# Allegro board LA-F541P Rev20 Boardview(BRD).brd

Outline 352.7 x 123.3 mm; copper layers: TOP, GND1, IN1, IN2, GND2, IN3, IN4, VCC, IN5, IN6, GND3, BOTTOM. Coordinates in mm from the lower left corner of the outline.

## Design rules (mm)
constraint set DEFAULT: min track width 0.14
net group CHR_USB20_1: nets CHR_USB20_N1 CHR_USB20_P1
net group CHR_USB20_1_R: nets CHR_USB20_N1_R CHR_USB20_P1_R
net group CHR_USB20_2: nets CHR_USB20_N2 CHR_USB20_P2
net group CHR_USB20_2_R: nets CHR_USB20_N2_R CHR_USB20_P2_R
net group CPU_DP3_0: nets CPU_DP3_N0 CPU_DP3_P0
net group CPU_DP3_1: nets CPU_DP3_N1 CPU_DP3_P1
net group CPU_DP3_2: nets CPU_DP3_N2 CPU_DP3_P2
net group CPU_DP3_3: nets CPU_DP3_N3 CPU_DP3_P3
net group CPU_DP3_AUX: nets CPU_DP3_AUXN CPU_DP3_AUXP
net group CPU_DP3_AUX_R: nets CPU_DP3_AUXN_R CPU_DP3_AUXP_R
net group CSI_ISL88738: nets CSIN_ISL88738 CSIP_ISL88738
net group CSO_ISL88738: nets CSON_ISL88738 CSOP_ISL88738
net group DIFFPAIR49: nets SD_RCLK_M SD_RCLK_P
net group DIFFPAIR63: nets TBT_DDC_CLK TBT_DDC_DATA
net group DIFFPAIR69: nets DDI1_DDPB_CTRLCLK DDI1_DDPB_CTRLDAT
net group DIFFPAIR70: nets DDI2_DDPC_CTRLCLK DDI2_DDPC_CTRLDAT
net group DIFFPAIR71: nets DTH_CSCL DTH_CSDA
net group DIFFPAIR79: nets I2C1_SCK_TP I2C1_SDA_TP
net group DIFFPAIR97: nets MSCLK MSDATA
net group DIFFPAIR98: nets MSCLK_R MSDATA_R
net group DIFFPAIR107: nets CPU_DP3_N0_C CPU_DP3_P0_C
net group DIFFPAIR108: nets CPU_DP3_N1_C CPU_DP3_P1_C
net group DIFFPAIR109: nets CPU_DP3_N2_C CPU_DP3_P2_C
net group DIFFPAIR110: nets CPU_DP3_N3_C CPU_DP3_P3_C
net group DIFFPAIR115: nets CPU_DP3_AUXN_C CPU_DP3_AUXP_C
net group DIFFPAIR120: nets PCIE_PRX_DTX_N11 PCIE_PRX_DTX_P11
net group DIFFPAIR122: nets VCCSENSE_VGA VSSSENSE_VGA
net group DIFFPAIR123: nets VCCGT_SENSE VSSGT_SENSE
net group DIFFPAIR124: nets VCC_SENSE VSS_SENSE
net group DIFFPAIR125: nets VCC_SENSE_R VSS_SENSE_R
net group DIFFPAIR126: nets VCCGT_SENSE_R VSSGT_SENSE_R
net group DIFFPAIR129: nets I2C0_SCK_TS_R I2C0_SDA_TS_R
net group DIFFPAIR130: nets PBAT_CHARGER_SMBCLK PBAT_CHARGER_SMBDAT
net group DIFFPAIR131: nets GPU_SMBCLK GPU_SMBDAT
net group DIFFPAIR132: nets MEM_SMBCLK MEM_SMBDATA
net group DIFFPAIR133: nets N128727776 N128727796
net group EDP_AUXP_C: nets EDP_AUXN_C EDP_AUXP_C
net group EDP_TX3_R: nets EDP_TXN3_R EDP_TXP3_R
net group EDP_TXP2_R: nets EDP_TXN2_R EDP_TXP2_R
net group ESPI_CLK: nets ESPI_CLK ESPI_CLK_5105
net group ESPI_IO0: nets ESPI_IO0 ESPI_IO0_R
net group ESPI_IO1: nets ESPI_IO1 ESPI_IO1_R
net group ESPI_IO2: nets ESPI_IO2 ESPI_IO2_R
net group ESPI_IO3: nets ESPI_IO3 ESPI_IO3_R
net group ESPI_RESET#: nets ESPI_RESET# ESPI_RESET#_R
net group FBA_CLK0: nets FBA_CLK0 FBA_CLK0#
net group FBA_CLK1: nets FBA_CLK1 FBA_CLK1#
net group FBA_WCK0: nets FBA_WCK0 FBA_WCK0_N
net group FBA_WCK1: nets FBA_WCK1 FBA_WCK1_N
net group FBA_WCK2: nets FBA_WCK2 FBA_WCK2_N
net group FBA_WCK3: nets FBA_WCK3 FBA_WCK3_N
net group FBC_CLK0: nets FBC_CLK0 FBC_CLK0#
net group FBC_CLK1: nets FBC_CLK1 FBC_CLK1#
net group FBC_WCK0: nets FBC_WCK0 FBC_WCK0_N
net group FBC_WCK1: nets FBC_WCK1 FBC_WCK1_N
net group FBC_WCK2: nets FBC_WCK2 FBC_WCK2_N
net group FBC_WCK3: nets FBC_WCK3 FBC_WCK3_N
net group HDMI-DDC: nets DDC_CLK_HDMI DDC_DAT_HDMI
net group ISUM_GT: nets ISUMN_GT ISUMP_GT
net group ISUM_SA: nets ISUMN_SA ISUMP_SA
net group ISUM_VCORE: nets ISUMN_VCORE ISUMP_VCORE
net group LPC_CLK: nets PCI_CLK_LPC1 PCI_CLK_LPC1_R
net group PCIE_PRX_C_TTX_17: nets PCIE_PRX_C_TTX_N17 PCIE_PRX_C_TTX_P17
net group PCIE_PRX_C_TTX_18: nets PCIE_PRX_C_TTX_N18 PCIE_PRX_C_TTX_P18
net group PCIE_PRX_C_TTX_19: nets PCIE_PRX_C_TTX_N19 PCIE_PRX_C_TTX_P19
net group PCIE_PRX_C_TTX_20: nets PCIE_PRX_C_TTX_N20 PCIE_PRX_C_TTX_P20
net group PCIE_PRX_TTX_17: nets PCIE_PRX_TTX_N17 PCIE_PRX_TTX_P17
net group PCIE_PRX_TTX_18: nets PCIE_PRX_TTX_N18 PCIE_PRX_TTX_P18
net group PCIE_PRX_TTX_19: nets PCIE_PRX_TTX_N19 PCIE_PRX_TTX_P19
net group PCIE_PRX_TTX_20: nets PCIE_PRX_TTX_N20 PCIE_PRX_TTX_P20
net group PCIE_PTX_C_TRX_17: nets PCIE_PTX_C_TRX_N17 PCIE_PTX_C_TRX_P17
net group PCIE_PTX_C_TRX_18: nets PCIE_PTX_C_TRX_N18 PCIE_PTX_C_TRX_P18
net group PCIE_PTX_C_TRX_19: nets PCIE_PTX_C_TRX_N19 PCIE_PTX_C_TRX_P19
net group PCIE_PTX_C_TRX_20: nets PCIE_PTX_C_TRX_N20 PCIE_PTX_C_TRX_P20
net group PCIE_PTX_TRX_17: nets PCIE_PTX_TRX_N17 PCIE_PTX_TRX_P17
net group PCIE_PTX_TRX_18: nets PCIE_PTX_TRX_N18 PCIE_PTX_TRX_P18
net group PCIE_PTX_TRX_19: nets PCIE_PTX_TRX_N19 PCIE_PTX_TRX_P19
net group PCIE_PTX_TRX_20: nets PCIE_PTX_TRX_N20 PCIE_PTX_TRX_P20
net group PCIE_RCOMP: nets PCIE_RCOMPN PCIE_RCOMPP
net group SD_RCLK_R: nets SD_RCLK_M_R SD_RCLK_P_R
net group TBT_RX/TX: nets TBT_USB3_TX0_N_C TBT_USB3_TX1_N_C
net group TBT_USB3_RX0_N: nets TBT_USB3_RX0_N TBT_USB3_RX0_N_R
net group TBT_USB3_RX0_P: nets TBT_USB3_RX0_P TBT_USB3_RX0_P_R
net group TBT_USB3_RX1_N: nets TBT_USB3_RX1_N TBT_USB3_RX1_N_R
net group TBT_USB3_RX1_P: nets TBT_USB3_RX1_P TBT_USB3_RX1_P_R
net group UART: nets UART2_RXD UART2_TXD
net group USB3_PRX_C_RD_DTX_1: nets USB3_PRX_C_RD_DTX_N1 USB3_PRX_C_RD_DTX_P1
net group USB3_PRX_DTX_1: nets USB3_PRX_DTX_N1 USB3_PRX_DTX_P1
net group USB3_PRX_DTX_2: nets USB3_PRX_DTX_N2 USB3_PRX_DTX_P2
net group USB3_PRX_L_DTX_1: nets USB3_PRX_L_DTX_N1 USB3_PRX_L_DTX_P1
net group USB3_PRX_RD_DTX_1: nets USB3_PRX_RD_DTX_N1 USB3_PRX_RD_DTX_P1
net group USB3_PTX_C_DRX_1: nets USB3_PTX_C_DRX_N1 USB3_PTX_C_DRX_P1
net group USB3_PTX_C_DRX_2: nets USB3_PTX_C_DRX_N2 USB3_PTX_C_DRX_P2
net group USB3_PTX_C_RD_DRX_1: nets USB3_PTX_C_RD_DRX_N1 USB3_PTX_C_RD_DRX_P1
net group USB3_PTX_DRX_1: nets USB3_PTX_DRX_N1 USB3_PTX_DRX_P1
net group USB3_PTX_DRX_2: nets USB3_PTX_DRX_N2 USB3_PTX_DRX_P2
net group USB3_PTX_L_DRX_1: nets USB3_PTX_L_DRX_N1 USB3_PTX_L_DRX_P1
net group USB3_PTX_RD_DRX_1: nets USB3_PTX_RD_DRX_N1 USB3_PTX_RD_DRX_P1
net group USB20_5: nets USB20_N5 USB20_P5
net group USB20_5_R: nets USB20_N5_R USB20_P5_R
net group USB20_9_R: nets USB20_N9_R USB20_P9_R
net group USBC_MCP23008_SMB: nets USBC_MCP23008_SMBCLK USBC_MCP23008_SMBDAT
net group ASY: nets CPU_TRIGGER CPU_TRIGGER_R DGPU_HOLD_RST# H_CATERR# H_CPUPWRGD H_PM_DOWN H_PM_DOWN_R H_PM_SYNC H_PM_SYNC_R H_PROCHOT# H_PROCHOT#_EC H_PROCHOT#_R H_THERMTRIP# H_THERMTRIP#_R H_VCCST_PWRGD INTRUDER# LPC_PD# PCH_DPWROK_EC PCH_DPWROK_R PCH_PCIE_WAKE# PCH_PWROK PCH_RSMRST# PCH_SYS_PWROK_XDP PCH_TRIGGER PCH_TRIGGER_R PLTRST_CPU# SIO_PWRBTN# SIO_RCIN# SYS_PWROK SYS_RESET# VCCST_PWRGD_CPU XDP_BPM#0 XDP_BPM#1
net group AUDIO: nets HPOUT_D_L_C HPOUT_D_R_C HPOUT_L HPOUT_L_R1 HPOUT_R HPOUT_R_R2 LINE1-VREFO LINE1_L LINE1_L_C LINE1_R LINE1_R_C MIC1-VREFO_L MIC1-VREFO_R SLEEVE_L
net group DDR_CLK: nets M_CLK_DDR0 M_CLK_DDR1 M_CLK_DDR2 M_CLK_DDR3 M_CLK_DDR#0 M_CLK_DDR#1 M_CLK_DDR#2 M_CLK_DDR#3
net group DDR_DQS: nets DDR_A_DQS0 DDR_A_DQS1 DDR_A_DQS2 DDR_A_DQS3 DDR_A_DQS4 DDR_A_DQS5 DDR_A_DQS6 DDR_A_DQS7 DDR_A_DQS#0 DDR_A_DQS#1 DDR_A_DQS#2 DDR_A_DQS#3 DDR_A_DQS#4 DDR_A_DQS#5 DDR_A_DQS#6 DDR_A_DQS#7 DDR_B_DQS0 DDR_B_DQS1 DDR_B_DQS2 DDR_B_DQS3 DDR_B_DQS4 DDR_B_DQS5 DDR_B_DQS6 DDR_B_DQS7 DDR_B_DQS#0 DDR_B_DQS#1 DDR_B_DQS#2 DDR_B_DQS#3 DDR_B_DQS#4 DDR_B_DQS#5 DDR_B_DQS#6 DDR_B_DQS#7
net group DDRA_ADD: nets DDR_A_ACT# DDR_A_ALERT# DDR_A_BG0 DDR_A_BG1 DDR_A_BS0 DDR_A_BS1 DDR_A_CAS# DDR_A_MA0 DDR_A_MA1 DDR_A_MA2 DDR_A_MA3 DDR_A_MA4 DDR_A_MA5 DDR_A_MA6 DDR_A_MA7 DDR_A_MA8 DDR_A_MA9 DDR_A_MA10 DDR_A_MA11 DDR_A_MA12 DDR_A_MA13 DDR_A_PAR DDR_A_RAS# DDR_A_WE#
net group DDRA_CTRL: nets DDR_CKE0_DIMMA DDR_CKE1_DIMMA DDR_CS0_DIMMA# DDR_CS1_DIMMA# M_ODT0 M_ODT1
net group DDRA_D0: nets DDR_A_D0 DDR_A_D1 DDR_A_D2 DDR_A_D3 DDR_A_D4 DDR_A_D5 DDR_A_D6 DDR_A_D7
net group DDRA_D1: nets DDR_A_D8 DDR_A_D9 DDR_A_D10 DDR_A_D11 DDR_A_D12 DDR_A_D13 DDR_A_D14 DDR_A_D15
net group DDRA_D2: nets DDR_A_D16 DDR_A_D17 DDR_A_D18 DDR_A_D19 DDR_A_D20 DDR_A_D21 DDR_A_D22 DDR_A_D23
net group DDRA_D3: nets DDR_A_D24 DDR_A_D25 DDR_A_D26 DDR_A_D27 DDR_A_D28 DDR_A_D29 DDR_A_D30 DDR_A_D31
net group DDRA_D4: nets DDR_A_D32 DDR_A_D33 DDR_A_D34 DDR_A_D35 DDR_A_D36 DDR_A_D37 DDR_A_D38 DDR_A_D39
net group DDRA_D5: nets DDR_A_D40 DDR_A_D41 DDR_A_D42 DDR_A_D43 DDR_A_D44 DDR_A_D45 DDR_A_D46 DDR_A_D47
net group DDRA_D6: nets DDR_A_D48 DDR_A_D49 DDR_A_D50 DDR_A_D51 DDR_A_D52 DDR_A_D53 DDR_A_D54 DDR_A_D55
net group DDRA_D7: nets DDR_A_D56 DDR_A_D57 DDR_A_D58 DDR_A_D59 DDR_A_D60 DDR_A_D61 DDR_A_D62 DDR_A_D63
net group DDRB_ADD: nets DDR_B_ACT# DDR_B_ALERT# DDR_B_BG0 DDR_B_BG1 DDR_B_BS0 DDR_B_BS1 DDR_B_CAS# DDR_B_MA0 DDR_B_MA1 DDR_B_MA2 DDR_B_MA3 DDR_B_MA4 DDR_B_MA5 DDR_B_MA6 DDR_B_MA7 DDR_B_MA8 DDR_B_MA9 DDR_B_MA10 DDR_B_MA11 DDR_B_MA12 DDR_B_MA13 DDR_B_PAR DDR_B_RAS# DDR_B_WE#
net group DDRB_CTRL: nets DDR_CKE2_DIMMB DDR_CKE3_DIMMB DDR_CS2_DIMMB# DDR_CS3_DIMMB# M_ODT2 M_ODT3
net group DDRB_D0: nets DDR_B_D0 DDR_B_D1 DDR_B_D2 DDR_B_D3 DDR_B_D4 DDR_B_D5 DDR_B_D6 DDR_B_D7
net group DDRB_D1: nets DDR_B_D8 DDR_B_D9 DDR_B_D10 DDR_B_D11 DDR_B_D12 DDR_B_D13 DDR_B_D14 DDR_B_D15
net group DDRB_D2: nets DDR_B_D16 DDR_B_D17 DDR_B_D18 DDR_B_D19 DDR_B_D20 DDR_B_D21 DDR_B_D22 DDR_B_D23
net group DDRB_D3: nets DDR_B_D24 DDR_B_D25 DDR_B_D26 DDR_B_D27 DDR_B_D28 DDR_B_D29 DDR_B_D30 DDR_B_D31
net group DDRB_D4: nets DDR_B_D32 DDR_B_D33 DDR_B_D34 DDR_B_D35 DDR_B_D36 DDR_B_D37 DDR_B_D38 DDR_B_D39
net group DDRB_D5: nets DDR_B_D40 DDR_B_D41 DDR_B_D42 DDR_B_D43 DDR_B_D44 DDR_B_D45 DDR_B_D46 DDR_B_D47
net group DDRB_D6: nets DDR_B_D48 DDR_B_D49 DDR_B_D50 DDR_B_D51 DDR_B_D52 DDR_B_D53 DDR_B_D54 DDR_B_D55
net group DDRB_D7: nets DDR_B_D56 DDR_B_D57 DDR_B_D58 DDR_B_D59 DDR_B_D60 DDR_B_D61 DDR_B_D62 DDR_B_D63
net group DIFFPAIR78: nets I2C0_SCK_TS
net group DIFFPAIR94: nets SML1_SMBDAT
net group DMI: nets DMI_CRX_PTX_N0 DMI_CRX_PTX_N1 DMI_CRX_PTX_N2 DMI_CRX_PTX_N3 DMI_CRX_PTX_P0 DMI_CRX_PTX_P1 DMI_CRX_PTX_P2 DMI_CRX_PTX_P3 DMI_CTX_PRX_N0 DMI_CTX_PRX_N1 DMI_CTX_PRX_N2 DMI_CTX_PRX_N3 DMI_CTX_PRX_P0 DMI_CTX_PRX_P1 DMI_CTX_PRX_P2 DMI_CTX_PRX_P3
net group EDP: nets EDP_AUXN EDP_AUXN_R EDP_AUXP EDP_AUXP_R EDP_HPD_S EDP_TXN0 EDP_TXN0_C EDP_TXN0_R EDP_TXN1 EDP_TXN1_C EDP_TXN1_R EDP_TXN2 EDP_TXN2_C EDP_TXN3 EDP_TXN3_C EDP_TXP0 EDP_TXP0_C EDP_TXP0_R EDP_TXP1 EDP_TXP1_C EDP_TXP1_R EDP_TXP2 EDP_TXP2_C EDP_TXP3 EDP_TXP3_C
net group ESPI: nets ESPI_ALERT#
net group FBA_CMD: nets FBA_ABI#_H FBA_ABI#_L FBA_CAS#_H FBA_CAS#_L FBA_CKE_H FBA_CKE_L FBA_CS#_H FBA_CS#_L FBA_MA0_MA10_H FBA_MA0_MA10_L FBA_MA1_MA9_H FBA_MA1_MA9_L FBA_MA2_BA0_H FBA_MA2_BA0_L FBA_MA3_BA3_H FBA_MA3_BA3_L FBA_MA4_BA2_H FBA_MA4_BA2_L FBA_MA5_BA1_H FBA_MA5_BA1_L FBA_MA6_MA11_H FBA_MA6_MA11_L FBA_MA7_MA8_H FBA_MA7_MA8_L FBA_MA12_RFU_H FBA_MA12_RFU_L FBA_RAS#_H FBA_RAS#_L FBA_RST#_H FBA_RST#_L FBA_WE#_H FBA_WE#_L
net group FBA_D0: nets FBA_D0 FBA_D1 FBA_D2 FBA_D3 FBA_D4 FBA_D5 FBA_D6 FBA_D7
net group FBA_D1: nets FBA_D8 FBA_D9 FBA_D10 FBA_D11 FBA_D12 FBA_D13 FBA_D14 FBA_D15
net group FBA_D2: nets FBA_D16 FBA_D17 FBA_D18 FBA_D19 FBA_D20 FBA_D21 FBA_D22 FBA_D23
net group FBA_D3: nets FBA_D24 FBA_D25 FBA_D26 FBA_D27 FBA_D28 FBA_D29 FBA_D30 FBA_D31
net group FBA_D4: nets FBA_D32 FBA_D33 FBA_D34 FBA_D35 FBA_D36 FBA_D37 FBA_D38 FBA_D39
net group FBA_D5: nets FBA_D40 FBA_D41 FBA_D42 FBA_D43 FBA_D44 FBA_D45 FBA_D46 FBA_D47
net group FBA_D6: nets FBA_D48 FBA_D49 FBA_D50 FBA_D51 FBA_D52 FBA_D53 FBA_D54 FBA_D55
net group FBA_D7: nets FBA_D56 FBA_D57 FBA_D58 FBA_D59 FBA_D60 FBA_D61 FBA_D62 FBA_D63
net group FBA_DBI: nets FBA_DBI0# FBA_DBI1# FBA_DBI2# FBA_DBI3# FBA_DBI4# FBA_DBI5# FBA_DBI6# FBA_DBI7#
net group FBA_EDC: nets FBA_EDC0 FBA_EDC1 FBA_EDC2 FBA_EDC3 FBA_EDC4 FBA_EDC5 FBA_EDC6 FBA_EDC7
net group FBC_CMD: nets FBC_ABI#_H FBC_ABI#_L FBC_CAS#_H FBC_CAS#_L FBC_CKE_H FBC_CKE_L FBC_CS#_H FBC_CS#_L FBC_MA0_MA10_H FBC_MA0_MA10_L FBC_MA1_MA9_H FBC_MA1_MA9_L FBC_MA2_BA0_H FBC_MA2_BA0_L FBC_MA3_BA3_H FBC_MA3_BA3_L FBC_MA4_BA2_H FBC_MA4_BA2_L FBC_MA5_BA1_H FBC_MA5_BA1_L FBC_MA6_MA11_H FBC_MA6_MA11_L FBC_MA7_MA8_H FBC_MA7_MA8_L FBC_MA12_RFU_H FBC_MA12_RFU_L FBC_RAS#_H FBC_RAS#_L FBC_RST#_H FBC_RST#_L FBC_WE#_H FBC_WE#_L
net group FBC_D0: nets FBC_D0 FBC_D1 FBC_D2 FBC_D3 FBC_D4 FBC_D5 FBC_D6 FBC_D7
net group FBC_D1: nets FBC_D8 FBC_D9 FBC_D10 FBC_D11 FBC_D12 FBC_D13 FBC_D14 FBC_D15
net group FBC_D2: nets FBC_D16 FBC_D17 FBC_D18 FBC_D19 FBC_D20 FBC_D21 FBC_D22 FBC_D23
net group FBC_D3: nets FBC_D24 FBC_D25 FBC_D26 FBC_D27 FBC_D28 FBC_D29 FBC_D30 FBC_D31
net group FBC_D4: nets FBC_D32 FBC_D33 FBC_D34 FBC_D35 FBC_D36 FBC_D37 FBC_D38 FBC_D39
net group FBC_D5: nets FBC_D40 FBC_D41 FBC_D42 FBC_D43 FBC_D44 FBC_D45 FBC_D46 FBC_D47
net group FBC_D6: nets FBC_D48 FBC_D49 FBC_D50 FBC_D51 FBC_D52 FBC_D53 FBC_D54 FBC_D55
net group FBC_D7: nets FBC_D56 FBC_D57 FBC_D58 FBC_D59 FBC_D60 FBC_D61 FBC_D62 FBC_D63
net group FBC_DBI: nets FBC_DBI0# FBC_DBI1# FBC_DBI2# FBC_DBI3# FBC_DBI4# FBC_DBI5# FBC_DBI6# FBC_DBI7#
net group FBC_EDC: nets FBC_EDC0 FBC_EDC1 FBC_EDC2 FBC_EDC3 FBC_EDC4 FBC_EDC5 FBC_EDC6 FBC_EDC7
net group GPU-CORESENSE: nets FBVDDQ_SENSE GNDS_SENSE_VGA VDDS_SENSE_VGA
net group HDA: nets AUD_AZA_CPU_SCLK AUD_AZA_CPU_SCLK_R AUD_AZA_CPU_SDI AUD_AZA_CPU_SDI_R AUD_AZA_CPU_SDO AUD_AZA_CPU_SDO_R HDA_BITCLK HDA_BITCLK_AUDIO HDA_RST# HDA_SDIN0 HDA_SDIN0_AUDIO HDA_SDOUT HDA_SDOUT_AUDIO HDA_SYNC HDA_SYNC_AUDIO I2S_BCLK I2S_IN I2S_LRCK I2S_MCLK I2S_OUT I2S_RST_AUDIO# I2S_RST_AUDIO#_R I2S_SDIN0_AUDIO_R
net group HDMI_12_15: nets HDMI_CLKN HDMI_CLKP HDMI_R_CLKN HDMI_R_CLKP HDMI_R_TX_N0 HDMI_R_TX_N1 HDMI_R_TX_N2 HDMI_R_TX_P0 HDMI_R_TX_P1 HDMI_R_TX_P2 HDMI_TX_N0 HDMI_TX_N1 HDMI_TX_N2 HDMI_TX_P0 HDMI_TX_P1 HDMI_TX_P2
net group I2C: nets BC_CLK_ECE1117 BC_DAT_ECE1117 CLK_TP_SIO DAT_TP_SIO DMIC_CLK_CODEC DMIC_CLK_CODEC_C DMIC_DAT_CODEC DMIC_DAT_CODEC_C EDP_PANEL_CLK EDP_PANEL_DAT I2C0_SCK_DSP I2C0_SDA_DSP I2C0_SDA_TS I2C1_SCK_TP_C I2C1_SDA_TP_C I2CB_SCL I2CB_SDA TBT_I2C_CLK TBT_I2C_CLK_R TBT_I2C_DATA TBT_I2C_DATA_R VGA_EDID_CLK VGA_EDID_DATA
net group N17-XTL: nets XTAL_OUT XTALIN XTALOUT XTALSSIN
net group PCIE: nets PCIE_PRX_C_DTX_N5 PCIE_PRX_C_DTX_P5 PCIE_PRX_DTX_N1 PCIE_PRX_DTX_N5 PCIE_PRX_DTX_N09 PCIE_PRX_DTX_N10 PCIE_PRX_DTX_P1 PCIE_PRX_DTX_P5 PCIE_PRX_DTX_P09 PCIE_PRX_DTX_P10 PCIE_PTX_C_DRX_N1 PCIE_PTX_C_DRX_N5 PCIE_PTX_C_DRX_N09 PCIE_PTX_C_DRX_N10 PCIE_PTX_C_DRX_N11 PCIE_PTX_C_DRX_P1 PCIE_PTX_C_DRX_P5 PCIE_PTX_C_DRX_P09 PCIE_PTX_C_DRX_P10 PCIE_PTX_C_DRX_P11 PCIE_PTX_DRX_N1 PCIE_PTX_DRX_N5 PCIE_PTX_DRX_N09 PCIE_PTX_DRX_N10 PCIE_PTX_DRX_N11 PCIE_PTX_DRX_P1 PCIE_PTX_DRX_P5 PCIE_PTX_DRX_P09 PCIE_PTX_DRX_P10 PCIE_PTX_DRX_P11
net group PECI: nets H_PECI H_PECI_R PCH_PECI PCIE_WAKE#
net group PEG: nets PEG_GTX_C_HRX_N0 PEG_GTX_C_HRX_N1 PEG_GTX_C_HRX_N2 PEG_GTX_C_HRX_N3 PEG_GTX_C_HRX_N4 PEG_GTX_C_HRX_N5 PEG_GTX_C_HRX_N6 PEG_GTX_C_HRX_N7 PEG_GTX_C_HRX_N8 PEG_GTX_C_HRX_N9 PEG_GTX_C_HRX_N10 PEG_GTX_C_HRX_N11 PEG_GTX_C_HRX_N12 PEG_GTX_C_HRX_N13 PEG_GTX_C_HRX_N14 PEG_GTX_C_HRX_N15 PEG_GTX_C_HRX_P0 PEG_GTX_C_HRX_P1 PEG_GTX_C_HRX_P2 PEG_GTX_C_HRX_P3 PEG_GTX_C_HRX_P4 PEG_GTX_C_HRX_P5 PEG_GTX_C_HRX_P6 PEG_GTX_C_HRX_P7 PEG_GTX_C_HRX_P8 PEG_GTX_C_HRX_P9 PEG_GTX_C_HRX_P10 PEG_GTX_C_HRX_P11 PEG_GTX_C_HRX_P12 PEG_GTX_C_HRX_P13 PEG_GTX_C_HRX_P14 PEG_GTX_C_HRX_P15 PEG_GTX_HRX_N0 PEG_GTX_HRX_N1 PEG_GTX_HRX_N2 PEG_GTX_HRX_N3 PEG_GTX_HRX_N4 PEG_GTX_HRX_N5 PEG_GTX_HRX_N6 PEG_GTX_HRX_N7 PEG_GTX_HRX_N8 PEG_GTX_HRX_N9 PEG_GTX_HRX_N10 PEG_GTX_HRX_N11 PEG_GTX_HRX_N12 PEG_GTX_HRX_N13 PEG_GTX_HRX_N14 PEG_GTX_HRX_N15 PEG_GTX_HRX_P0 PEG_GTX_HRX_P1 PEG_GTX_HRX_P2 PEG_GTX_HRX_P3 PEG_GTX_HRX_P4 PEG_GTX_HRX_P5 PEG_GTX_HRX_P6 PEG_GTX_HRX_P7 PEG_GTX_HRX_P8 PEG_GTX_HRX_P9 PEG_GTX_HRX_P10 PEG_GTX_HRX_P11 PEG_GTX_HRX_P12 PEG_GTX_HRX_P13 PEG_GTX_HRX_P14 PEG_GTX_HRX_P15 PEG_HTX_C_GRX_N0 PEG_HTX_C_GRX_N1 PEG_HTX_C_GRX_N2 PEG_HTX_C_GRX_N3 PEG_HTX_C_GRX_N4 PEG_HTX_C_GRX_N5 PEG_HTX_C_GRX_N6 PEG_HTX_C_GRX_N7 PEG_HTX_C_GRX_N8 PEG_HTX_C_GRX_N9 PEG_HTX_C_GRX_N10 PEG_HTX_C_GRX_N11 PEG_HTX_C_GRX_N12 PEG_HTX_C_GRX_N13 PEG_HTX_C_GRX_N14 PEG_HTX_C_GRX_N15 PEG_HTX_C_GRX_P0 PEG_HTX_C_GRX_P1 PEG_HTX_C_GRX_P2 PEG_HTX_C_GRX_P3 PEG_HTX_C_GRX_P4 PEG_HTX_C_GRX_P5 PEG_HTX_C_GRX_P6 PEG_HTX_C_GRX_P7 PEG_HTX_C_GRX_P8 PEG_HTX_C_GRX_P9 PEG_HTX_C_GRX_P10 PEG_HTX_C_GRX_P11 PEG_HTX_C_GRX_P12 PEG_HTX_C_GRX_P13 PEG_HTX_C_GRX_P14 PEG_HTX_C_GRX_P15 PEG_HTX_GRX_N0 PEG_HTX_GRX_N1 PEG_HTX_GRX_N2 PEG_HTX_GRX_N3 PEG_HTX_GRX_N4 PEG_HTX_GRX_N5 PEG_HTX_GRX_N6 PEG_HTX_GRX_N7 PEG_HTX_GRX_N8 PEG_HTX_GRX_N9 PEG_HTX_GRX_N10 PEG_HTX_GRX_N11 PEG_HTX_GRX_N12 PEG_HTX_GRX_N13 PEG_HTX_GRX_N14 PEG_HTX_GRX_N15 PEG_HTX_GRX_P0 PEG_HTX_GRX_P1 PEG_HTX_GRX_P2 PEG_HTX_GRX_P3 PEG_HTX_GRX_P4 PEG_HTX_GRX_P5 PEG_HTX_GRX_P6 PEG_HTX_GRX_P7 PEG_HTX_GRX_P8 PEG_HTX_GRX_P9 PEG_HTX_GRX_P10 PEG_HTX_GRX_P11 PEG_HTX_GRX_P12 PEG_HTX_GRX_P13 PEG_HTX_GRX_P14 PEG_HTX_GRX_P15
net group PLATFORM CLK: nets CLK_PCIE_N3 CLK_PCIE_N4 CLK_PCIE_N5 CLK_PCIE_N6 CLK_PCIE_N7 CLK_PCIE_P3 CLK_PCIE_P4 CLK_PCIE_P5 CLK_PCIE_P6 CLK_PCIE_P7 CPU_24MHZ_N CPU_24MHZ_P PCH_CPU_BCLK_N PCH_CPU_BCLK_P PCH_CPU_PCIBCLK_N PCH_CPU_PCIBCLK_P PCH_XDP_CLK_N PCH_XDP_CLK_P
net group PLATFORM CLOCK-SE: nets XCLK_BIASREF XTAL24_IN XTAL24_IN_R XTAL24_OUT XTAL24_OUT_R
net group PWM: nets BIA_PWM_EC BIA_PWM_EC_R BIA_PWM_PCH INV_PWM PWM_FAN1 PWM_FAN2 TACH_FAN1 TACH_FAN2
net group PWR: nets +3VALWP +3VLP +5VALWP +RTCBATT +V_DDR_REF +V_DDR_REFA_R +V_DDR_REFB_R
net group RTC: nets 32KHZ_OUT MEC_XTAL1 MEC_XTAL2 MEC_XTAL2_R PCH_RTCRST# PCH_RTCX1 PCH_RTCX2 PCH_SRTCRST# SUSCLK SUSCLK_R
net group SATA: nets SATA_PRX_C_DTX_N2 SATA_PRX_C_DTX_P2 SATA_PRX_DTX_N1A SATA_PRX_DTX_N2 SATA_PRX_DTX_P1A SATA_PRX_DTX_P2 SATA_PTX_C_DRX_N1A SATA_PTX_C_DRX_N2 SATA_PTX_C_DRX_P1A SATA_PTX_C_DRX_P2 SATA_PTX_DRX_N1A SATA_PTX_DRX_N2 SATA_PTX_DRX_P1A SATA_PTX_DRX_P2
net group SD: nets SD_CD# SD_CLK SD_CLK_R SD_CMD SD_CMD_R SD_D2 SD_D2_R SD_D3 SD_D3_R SD_REG2
net group SD4.0: nets SD_LN0_M SD_LN0_P SD_LN1_M SD_LN1_P
net group SMB: nets AUDIO_AMP_SMBCLK AUDIO_AMP_SMBDAT CLINK_CLK CLINK_DATA DOCK_TNY_SMB_CLK DOCK_TNY_SMB_DAT EC_SMB_CK2_PX EC_SMB_DA2_PX PCH_DMIC_CLK PCH_DMIC_CLK_R PCH_DMIC_DAT PCH_DMIC_DAT_R PCH_SMBCLK PCH_SMBDATA SML0_SMBCLK SML0_SMBDATA SML1_SMBCLK TBT_LSRX TBT_LSTX TBTA_DEBUG1 TBTA_DEBUG2 TBTA_DEBUG3_LSTX TBTA_DEBUG4_LSRX UPD_SMBCLK UPD_SMBDAT
net group SPI: nets DTH_SPI_CK_OUT DTH_SPI_CS DTH_SPI_D_IN DTH_SPI_D_OUT DTH_SPI_WR_PROT PCH_SPI_CLK PCH_SPI_CLK_R PCH_SPI_CLK_TPM PCH_SPI_CLK_TPM_R PCH_SPI_CS#0 PCH_SPI_CS#1 PCH_SPI_CS#2 PCH_SPI_CS#2_R PCH_SPI_HOLD# PCH_SPI_HOLD#_R PCH_SPI_SI PCH_SPI_SI_R PCH_SPI_SI_TPM PCH_SPI_SI_TPM_R PCH_SPI_SO PCH_SPI_SO_R PCH_SPI_SO_TPM PCH_SPI_SO_TPM_R PCH_SPI_WP# PCH_SPI_WP#_R TBT_ROM_CLK TBT_ROM_CS# TBT_ROM_DI TBT_ROM_DO TBT_ROM_HOLD# TBT_ROM_WP#
net group SVID: nets VR_SVID_ALERT# VR_SVID_ALERT#_C VR_SVID_ALERT#_R VR_SVID_CLK VR_SVID_CLK_C VR_SVID_DATA VR_SVID_DATA_C
net group TBT-DP-AR: nets CPU_DP2_AUXN CPU_DP2_AUXN_C CPU_DP2_AUXP CPU_DP2_AUXP_C CPU_DP2_N0 CPU_DP2_N0_C CPU_DP2_N1 CPU_DP2_N1_C CPU_DP2_N2 CPU_DP2_N2_C CPU_DP2_N3 CPU_DP2_N3_C CPU_DP2_P0 CPU_DP2_P0_C CPU_DP2_P1 CPU_DP2_P1_C CPU_DP2_P2 CPU_DP2_P2_C CPU_DP2_P3 CPU_DP2_P3_C
net group TBT-DP-PS1752: nets CPU_DP1_AUXN CPU_DP1_AUXN_C CPU_DP1_AUXP CPU_DP1_AUXP_C CPU_DP1_N0 CPU_DP1_N0_C CPU_DP1_N1 CPU_DP1_N1_C CPU_DP1_N2 CPU_DP1_N2_C CPU_DP1_N3 CPU_DP1_N3_C CPU_DP1_P0 CPU_DP1_P0_C CPU_DP1_P1 CPU_DP1_P1_C CPU_DP1_P2 CPU_DP1_P2_C CPU_DP1_P3 CPU_DP1_P3_C
net group TBT-JUSBC: nets TBT_USB2_D+ TBT_USB2_D- TBT_USB3_TX0_N TBT_USB3_TX0_P TBT_USB3_TX0_P_C TBT_USB3_TX1_N TBT_USB3_TX1_P TBT_USB3_TX1_P_C TBTA_AUX_N TBTA_AUX_N_C TBTA_AUX_P TBTA_AUX_P_C TBTA_BOT_C_N TBTA_BOT_C_P TBTA_BOT_N TBTA_BOT_P TBTA_PD_SBU1 TBTA_PD_SBU2 TBTA_SBU1 TBTA_SBU2 TBTA_TOP_C_N TBTA_TOP_C_P TBTA_TOP_N TBTA_TOP_P
net group THERMAL DIODE: nets REM_DIODE1_N REM_DIODE1_P REM_DIODE2_N REM_DIODE2_P REM_DIODE3_N REM_DIODE3_P REM_DIODE4_N REM_DIODE4_P
net group USB2.0: nets USB20_FP_N7_CONN USB20_FP_P7_CONN USB20_N1 USB20_N2 USB20_N4 USB20_N4_R USB20_N7 USB20_N9 USB20_N12 USB20_N12_R USB20_P1 USB20_P2 USB20_P4 USB20_P4_R USB20_P7 USB20_P9 USB20_P12 USB20_P12_R
net group X-TAL: nets DTH_XTLI DTH_XTLO XTAL_25_IN XTAL_25_IN_R XTAL_25_OUT XTAL_25_OUT_R
nets with their own width: min track width 0.203; nets VCC1V8A_TBTA_LDO
nets with their own width: min track width 0.254; nets GPU_CORE_PG N132908405 N132908425 N132908471 N132908575 N132908582 NVVDD_EN NVVDDS_EN TBTA_CC1 TBTA_CC2 VCC_3V3_PCIE VCC_3V3_USB2
nets with their own width: min track width 0.381; nets +PEX_PLL_HVDD +PEX_SVDD_3V3 N130500830
nets with their own width: min track width 0.406; nets +FBA_VREFC0
nets with their own width: min track width 0.508; nets +0.6VS +0.6VSP +0.95VSP +1.2V_DDR +1.2V_DTH +1.2V_MEN_P +1.2V_PWROK +1.2V_VCCPLL_OC +1.35VSDGPU +1V_PCH +1V_PCH_AZPLL +1V_PCH_PRIM +1V_VCCDSW +1VALW +1VSP +3V_PCH +3V_PCH_AZIO +3V_PCH_DSW +3V_ROM +3V_TBT +3VA_TBT +3VA_TBT_LC +3VALW +3VALW_5105 +3VS +3VS_CAM +3VS_CR +3VS_DTH +3VS_FFS +3VS_TP +3VS_TPM_VSB +3VS_TS +3VS_WLAN +5V_CHGUSB_1 +5V_CHGUSB_2 +5VALW +5VS +AC_IN +DC_IN +DC_IN_SS +GPU_CORE +GPU_CORE_VDDS +ODR_PWR +RTC_CELL_VBAT +RTCVCC +RTCVCC_R +SD_VDD2 +SDC_IN +V_DDR_REFA +V_DDR_REFB +VBUS_1 +VBUS_DC_SS +VCC0V9_PCIE +VCC0V9_USB +VCC_CORE +VCCGT +VCCIO +VCCSA +VCCST +VCCSTG +VGA_B+ +VLDOIN_1.2V +VR_CAP AGND B+ B++ DGPU_PEX_RST# DTH_VDD12 DTH_VDD33 DTH_VDDA12 DTH_VDDRX12 DTH_VDDTX12 EDP_COMP GND MEM_VREF RING2_L VCC3V3_FLASH VCC5V0_SYS
nets with their own width: min track width 1.016; nets 5VS_FAN1 5VS_FAN2 +VDISPLAY_VCC RING2 SLEEVE
nets with their own width: min track width 1.27; nets +5VS_HDD
nets with their own width: min track width 1.524; nets +EDPVDD +INV_PWR_SRC
nets with their own width: min track width 2.54; nets +3.3VDX_SSD

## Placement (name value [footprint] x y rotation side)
ADP100  ACES_50290-00701-001  [ACES_50290-00701-001_7P-T]  20.6 80.35 90 bottom
BAT100  ACES_50290-01201-P01  [ACES_50290-01201-P01_12P-T]  28.32 12.07 180 bottom
C2  22P_0201_25V8  [C_0201]  172.84 3.6 180 top
C3  1U_0402_6.3V6K~D  [C_0402]  169.67 6.48 270 top
C4  0.1U_0201_10V6K  [C_0201]  175.67 6.73 270 top
C135  0.1U_0201_10V6K  [C_0201]  149.52 9.27 180 top
C267  1U_0402_6.3V6K  [C_0402]  339.47 100.64 90 top
C280  0.1U_0201_10V6K  [C_0201]  336.78 100.82 90 top
C1031  100P_0201_50V8J  [C_0201]  337.34 100.82 90 top
C1033  68P_0402_50V8J  [C_0402]  338.07 100.64 90 top
C1079  2.2U_0402_6.3V6M  [C_0402]  315.8 26.67 180 bottom
C1080  0.1U_0201_10V6K  [C_0201]  313.86 34.29 180 bottom
C3003  0.1U_0201_10V6K  [C_0201]  350.61 60.07 0 bottom
C3004  0.1U_0201_10V6K  [C_0201]  345.95 46.7 0 bottom
C3005  10U_0402_6.3V6M  [C_0402]  346.46 60.12 90 bottom
C3319  0.1U_0201_10V6K  [C_0201]  306.57 13.42 0 top
C3320  2200P_0402_50V7K  [C_0402]  310.39 6.86 180 top
C3321  2200P_0402_50V7K  [C_0402]  311.53 11.3 0 top
CA1  0.1U_0201_6.3V6K  [C_0201]  12.64 35.78 180 top
CA2  10U_0402_6.3V6M  [C_0402]  14.02 36.96 0 top
CA3  0.1U_0201_6.3V6K  [C_0201]  12.68 38.61 180 top
CA4  10U_0402_6.3V6M  [C_0402]  12.65 37.78 180 top
CA5  0.1U_0201_6.3V6K  [C_0201]  13.4 41.52 90 bottom
CA6  10U_0402_6.3V6M  [C_0402]  14.17 41.47 90 bottom
CA7  10U_0402_6.3V6M  [C_0402]  15.16 41.47 90 bottom
CA8  0.1U_0201_6.3V6K  [C_0201]  15.14 38.36 0 bottom
CA9  10U_0402_6.3V6M  [C_0402]  15.1 37.59 0 bottom
CA10  0.1U_0201_6.3V6K  [C_0201]  13.53 39.54 270 bottom
CA11  10U_0402_6.3V6M  [C_0402]  14.25 39.96 270 bottom
CA12  0.1U_0201_6.3V6K  [C_0201]  3.08 40.25 180 top
CA13  10U_0402_6.3V6M  [C_0402]  3.25 41.91 180 top
CA14  10U_0402_6.3V6M  [C_0402]  3.25 41.02 180 top
CA15  2.2U_0402_6.3V6K  [C_0402]  3.68 40.25 180 bottom
CA16  0.1U_0201_6.3V6K  [C_0201]  2.25 39.31 0 bottom
CA17  0.1U_0201_6.3V6K  [C_0201]  3.09 39.56 180 top
CA18  2.2U_0402_6.3V6K  [C_0402]  3.68 41.59 180 bottom
CA19  100P_0201_25V8J  [C_0201]  2.24 29.71 0 top
CA20  2.2U_0402_6.3V6K  [C_0402]  3.32 42.89 90 bottom
CA21  2.2U_0402_6.3V6K  [C_0402]  5.59 43.88 180 bottom
CA23  0.1U_0201_6.3V6K  [C_0201]  5.25 29.65 270 bottom
CA24  0.1U_0201_6.3V6K  [C_0201]  12.95 43.76 180 bottom
CA25  2.2U_0402_6.3V6M  [C_0402]  13.06 44.7 90 bottom
CA26  0.1U_0201_6.3V6K  [C_0201]  2.82 38.1 0 top
CA27  10U_0402_6.3V6M  [C_0402]  2.73 37.35 270 top
CA28  0.1U_0201_6.3V6K  [C_0201]  2.83 38.1 180 bottom
CA29  4.7U_0402_6.3V6M  [C_0402]  2.8 37.35 270 bottom
CA30  10U_0402_6.3V6M  [C_0402]  13.95 45.06 90 bottom
CA31  10U_0402_6.3V6M  [C_0402]  11.47 43.7 90 bottom
CA32  0.1U_0201_6.3V6K  [C_0201]  9.06 33.74 180 bottom
CA33  8.2P_0201_50V8B  [C_0201]  5.04 33.48 180 bottom
CA34  10P_0201_50V8J  [C_0201]  5.12 34.1 180 bottom
CA35  10P_0201_50V8J  [C_0201]  13.67 35.43 270 top
CA36  10P_0201_50V8J  [C_0201]  13.4 35.5 270 bottom
CA37  10P_0201_50V8J  [C_0201]  4.67 29.63 270 bottom
CA38  10P_0201_50V8J  [C_0201]  4.03 32.36 90 top
CA39  4.7U_0402_6.3V6M  [C_0402]  5.64 32.96 180 top
CA40  0.1U_0201_6.3V6K  [C_0201]  6.03 36.15 90 top
CA41  680P_0402_50V7K  [C_0402]  6.49 59.09 180 bottom
CA42  680P_0402_50V7K  [C_0402]  13.42 51.35 90 bottom
CA43  680P_0402_50V7K  [C_0402]  13.97 47.32 270 top
CA44  680P_0402_50V7K  [C_0402]  5.26 45.54 270 top
CA45  10U_0402_6.3V6M  [C_0402]  8.18 43.31 0 top
CA77  4.7U_0402_6.3V6M  [C_0402]  4.51 34.75 270 top
CA78  4.7U_0402_6.3V6M  [C_0402]  9.35 32.98 180 bottom
CA119  10U_0402_6.3V6M  [C_0402]  7.67 42.36 0 top
CA120  22P_0201_25V8  [C_0201]  4.46 32.84 0 bottom
CA121  1U_0201_6.3V6M  [C_0201]  5.98 11.14 0 bottom
CA122  1U_0201_6.3V6M  [C_0201]  7.62 12.32 0 bottom
CA124  470P_0201_25V7K  [C_0201]  8.89 9.36 90 top
CA125  1000P_0201_16V7K  [C_0201]  9.53 9.36 90 top
CA126  1U_0201_6.3V6M  [C_0201]  8.48 4.36 0 top
CA127  1U_0201_6.3V6M  [C_0201]  11.8 5.53 0 top
CA128  10U_0402_6.3V6M  [C_0402]  4.83 8.76 180 top
CA129  10U_0402_6.3V6M  [C_0402]  11.69 8.46 270 top
CA130  0.1U_0201_6.3V6K  [C_0201]  4.32 36.11 270 top
CA131  4.7U_0402_6.3V6M  [C_0402]  87.01 13.07 180 top
CD1  1U_0402_6.3V6K  [C_0402]  147.77 29.05 90 top
CD2  1U_0402_6.3V6K  [C_0402]  135.89 30.03 270 top
CD3  1U_0402_6.3V6K  [C_0402]  181.56 22.08 0 top
CD4  1U_0402_6.3V6K  [C_0402]  181.56 21.2 0 top
CD5  10U_0603_6.3V6M  [C_0603]  149.54 28.75 90 top
CD6  10U_0603_6.3V6M  [C_0603]  141.61 22.1 0 top
CD7  10U_0603_6.3V6M  [C_0603]  125.02 29.58 0 top
CD8  10U_0603_6.3V6M  [C_0603]  138.62 30.14 270 top
CD9  10U_0603_6.3V6M  [C_0603]  179.95 20.13 0 top
CD10  10U_0603_6.3V6M  [C_0603]  179.95 18.92 0 top
CD11  220U_D7_2VM_R6M  [C_EEFSS0D221R]  159.35 31.62 0 top
CD12  1U_0402_6.3V6K  [C_0402]  173.8 19.43 90 top
CD13  10U_0603_6.3V6M  [C_0603]  174.88 19.1 90 top
CD14  10U_0603_6.3V6M  [C_0603]  176.15 18.97 90 top
CD15  10U_0603_6.3V6M  [C_0603]  177.42 18.97 90 top
CD16  .1U_0402_16V7K  [C_0402]  171.82 28.38 180 top
CD17  2.2U_0402_6.3V6M  [C_0402]  171.93 27.3 180 top
CD18  .1U_0402_16V7K  [C_0402]  150.19 19.15 90 top
CD19  1U_0402_6.3V6K  [C_0402]  211.23 22.23 90 top
CD20  1U_0402_6.3V6K  [C_0402]  213.08 22.23 90 top
CD21  1U_0402_6.3V6K  [C_0402]  190.89 20.64 90 top
CD22  1U_0402_6.3V6K  [C_0402]  215.86 19.74 90 top
CD23  10U_0603_6.3V6M  [C_0603]  217.08 30.14 270 top
CD24  10U_0603_6.3V6M  [C_0603]  219.09 21.22 90 top
CD25  10U_0603_6.3V6M  [C_0603]  168.82 29.99 270 top
CD26  10U_0603_6.3V6M  [C_0603]  196.62 21.32 90 top
CD27  10U_0603_6.3V6M  [C_0603]  244.41 30.67 270 top
CD28  10U_0603_6.3V6M  [C_0603]  242.63 30.67 270 top
CD29  .1U_0402_16V7K  [C_0402]  227.37 19.05 0 top
CD30  1U_0402_6.3V6K  [C_0402]  246.13 30.68 270 top
CD31  1U_0402_6.3V6K  [C_0402]  247.14 30.68 270 top
CD32  1U_0402_6.3V6K  [C_0402]  255.09 17.97 90 top
CD33  220U_D7_2VM_R6M  [C_EEFSS0D221R]  212.55 31.69 180 top
CD34  .1U_0402_16V7K  [C_0402]  250.71 24.77 180 top
CD35  2.2U_0402_6.3V6M  [C_0402]  250.71 25.66 180 top
CD36  4.7U_0603_6.3V6K  [C_0603]  268.54 22.1 180 top
CD37  0.22U_0402_10V6K  [C_0402]  256.69 11.69 0 bottom
CD38  .1U_0402_16V7K  [C_0402]  268.56 20.07 180 top
CD39  0.01U_0402_16V7K  [C_0402]  268.56 19.05 180 top
CD40  47P_0402_50V8J  [C_0402]  268.43 4.95 180 top
CD41  15P_0402_50V8J  [C_0402]  268.43 5.97 180 top
CD42  0.22U_0402_10V6K  [C_0402]  256.69 10.8 0 bottom
CD43  0.22U_0402_10V6K  [C_0402]  257.1 20.7 0 bottom
CD44  0.22U_0402_10V6K  [C_0402]  257.1 19.81 0 bottom
CD45  0.22U_0402_10V6K  [C_0402]  256.95 17.65 0 bottom
CD46  0.22U_0402_10V6K  [C_0402]  256.95 16.77 0 bottom
CD51  0.22U_0402_10V6K  [C_0402]  256.69 13.84 0 bottom
CD53  0.22U_0402_10V6K  [C_0402]  256.69 14.73 0 bottom
CD69  .1U_0402_16V7K  [C_0402]  133.48 15.7 180 top
CD70  10U_0603_6.3V6M  [C_0603]  145.66 20.94 90 top
CD71  10U_0603_6.3V6M  [C_0603]  148.38 21.01 90 top
CD72  10U_0603_6.3V6M  [C_0603]  140.78 30.14 270 top
CD73  10U_0603_6.3V6M  [C_0603]  133.57 29.83 0 top
CD74  1U_0402_6.3V6K  [C_0402]  139.36 21.54 90 top
CD75  1U_0402_6.3V6K  [C_0402]  137.16 21.54 90 top
CD76  1U_0402_6.3V6K  [C_0402]  135.09 21.08 90 top
CD77  1U_0402_6.3V6K  [C_0402]  133.15 21.54 90 top
CD78  1U_0402_6.3V6K  [C_0402]  143.56 30.02 270 top
CD79  1U_0402_6.3V6K  [C_0402]  142.16 30.02 270 top
CD80  1U_0402_6.3V6K  [C_0402]  224.07 29.05 90 top
CD81  1U_0402_6.3V6K  [C_0402]  219.86 30.02 270 top
CD82  1U_0402_6.3V6K  [C_0402]  218.46 30.02 270 top
CD83  1U_0402_6.3V6K  [C_0402]  215.35 22.34 90 top
CD84  10U_0603_6.3V6M  [C_0603]  228.02 20.66 90 top
CD85  10U_0603_6.3V6M  [C_0603]  225.84 28.75 90 top
CD86  10U_0603_6.3V6M  [C_0603]  224.18 20.51 90 top
CD87  10U_0603_6.3V6M  [C_0603]  221.57 20.12 90 top
CD88  10U_0603_6.3V6M  [C_0603]  256.48 14.23 0 top
CD89  10U_0603_6.3V6M  [C_0603]  256.48 15.55 0 top
CD90  10U_0603_6.3V6M  [C_0603]  256.48 16.82 0 top
CD3324  2P_0201_25V8B  [C_0201]  92.76 3.69 0 top
CD3325  2P_0201_25V8B  [C_0201]  106.99 2.71 180 bottom
CD3326  .1U_0402_16V7K  [C_0402]  133.48 17.53 180 top
CD3327  .1U_0402_16V7K  [C_0402]  133.48 16.61 180 top
CD3328  .1U_0402_16V7K  [C_0402]  131.57 92.33 0 top
CE2  0.1U_0402_10V6K  [C_0402]  190.39 8.47 270 top
CE11  0.1U_0201_25V6K  [C_0201]  158.55 5.97 0 top
CE15  0.1U_0201_10V6K  [C_0201]  349.51 117.23 270 top
CE16  10P_0201_50V8J  [C_0201]  348.06 117.23 270 top
CE17  0.1U_0402_25V6  [C_0402]  284.46 17.02 90 top
CE18  0.1U_0402_25V6  [C_0402]  298.25 6.43 0 top
CE19  22U_0603_6.3V6M  [C_0603]  298.02 7.47 0 top
CE20  0.1U_0402_25V6  [C_0402]  300.51 7.11 0 top
CE22  10U_0603_6.3V6M  [C_0603]  312.23 15.75 0 top
CE23  0.1U_0402_25V6  [C_0402]  309.42 16.77 0 top
CE24  1U_0402_6.3V6K  [C_0402]  306.38 18.61 0 top
CE25  0.1U_0402_25V6  [C_0402]  296.98 7.72 270 top
CE26  0.1U_0402_25V6  [C_0402]  291.72 14.17 180 top
CE27  0.1U_0402_25V6  [C_0402]  306.71 7.7 270 top
CE29  1U_0402_6.3V6K  [C_0402]  287.45 19.18 0 top
CE30  2.2U_0402_6.3V6M  [C_0402]  288.37 15.11 180 top
CE31  0.047U_0402_25V7K  [C_0402]  306.38 19.5 0 top
CE32  2200P_0402_25V7K  [C_0402]  291.72 15.95 270 top
CE33  2200P_0402_25V7K  [C_0402]  291.72 18.75 270 top
CE34  0.1U_0402_25V6  [C_0402]  303.28 25.25 90 top
CE35  2200P_0402_25V7K  [C_0402]  290.32 17.48 270 top
CE36  2200P_0402_25V7K  [C_0402]  290.32 20.27 270 top
CE37  1U_0402_6.3V6K  [C_0402]  290.92 4.09 180 top
CE38  1U_0402_6.3V6K  [C_0402]  292.63 4.95 270 top
CE39  47P_0402_50V8J  [C_0402]  305.18 25.32 90 top
CE40  1U_0603_10V6K  [C_0603]  304.55 7.68 270 top
CE41  0.1U_0402_25V6  [C_0402]  288.24 21.21 180 top
CE42  10P_0402_50V8J  [C_0402]  290.51 9.84 270 top
CE43  12P_0201_50V8J  [C_0201]  290.51 10.7 90 top
CE44  1U_0402_6.3V6K  [C_0402]  299.16 22.76 180 top
CE45  100P_0402_50V8J  [C_0402]  115.3 112.38 270 bottom
CE46  100P_0402_50V8J  [C_0402]  175.44 120.78 180 bottom
CE47  100P_0402_50V8J  [C_0402]  189 48.75 0 top
CE48  4.7P_0402_50V8C  [C_0402]  294.07 32.65 270 top
CE49  100P_0402_50V8J  [C_0402]  182 49.28 90 bottom
CE50  100P_0402_50V8J  [C_0402]  281.89 25.91 180 bottom
CE51  4700P_0402_25V7K  [C_0402]  300.91 22.43 90 top
CE52  0.1U_0402_25V6  [C_0402]  303.49 7.58 270 top
CE65  2200P_0402_25V7K  [C_0402]  193.66 9.37 0 top
CE66  0.01U_0402_16V7K  [C_0402]  103.28 34.51 0 top
CE67  0.01U_0402_16V7K  [C_0402]  335.03 48.24 270 bottom
CE68  100P_0402_50V8J  [C_0402]  29.61 51.23 90 bottom
CE69  100P_0402_50V8J  [C_0402]  158.33 72.58 0 top
CE70  1U_0402_6.3V6K  [C_0402]  286.96 13.92 270 top
CE71  1U_0402_6.3V6K  [C_0402]  284.94 14.8 180 top
CE72  100P_0402_50V8J  [C_0402]  241.38 106.81 180 bottom
CE73  4.7P_0402_50V8C  [C_0402]  154.43 11.69 270 bottom
CE74  4.7P_0402_50V8C  [C_0402]  154.43 9.91 270 bottom
CE75  0.1U_0201_25V6K  [C_0201]  158.55 9.53 0 top
CE76  10U_0603_6.3V6M  [C_0603]  158.18 10.44 0 top
CE77  22P_0402_50V8J  [C_0402]  193.17 13.46 0 bottom
CE78  22P_0402_50V8J  [C_0402]  192.28 13.46 180 bottom
CE79  22P_0402_50V8J  [C_0402]  187.85 13.41 90 bottom
CE80  22P_0402_50V8J  [C_0402]  186.9 13.41 90 bottom
CE81  4.7P_0402_50V8C  [C_0402]  165.15 9.15 0 bottom
CE82  4.7P_0402_50V8C  [C_0402]  165.15 10.03 0 bottom
CE83  10U_0603_6.3V6M  [C_0603]  153.44 6.97 180 bottom
CE84  0.1U_0201_25V6K  [C_0201]  149.81 5.34 180 top
CE85  0.1U_0201_25V6K  [C_0201]  149.82 6.1 180 top
CE1501  10P_0402_50V8J  [C_0402]  296.93 4.75 0 top
CE3319  4700P_0402_25V7K  [C_0402]  278.43 14.14 180 top
CE3321  27P_0402_50V8J  [C_0402]  149.52 10.72 180 bottom
CE3322  27P_0402_50V8J  [C_0402]  151.38 8.44 90 bottom
CE3323  0.1U_0402_25V6  [C_0402]  202.57 51.99 90 top
CF1  10U_0603_6.3V6M  [C_0603]  240.44 46.37 270 top
CF2  0.1U_0402_25V6  [C_0402]  239.9 48.64 90 top
CH3  0.1U_0402_25V6  [C_0402]  121.76 96.09 270 bottom
CH5  0.22U_0201_6.3V6M  [C_0201]  188 83.53 0 bottom
CH6  0.22U_0201_6.3V6M  [C_0201]  188 84.16 0 bottom
CH7  0.22U_0201_6.3V6M  [C_0201]  187.99 81.47 0 bottom
CH8  0.22U_0201_6.3V6M  [C_0201]  187.99 82.11 0 bottom
CH9  0.22U_0201_6.3V6M  [C_0201]  189.45 80.2 0 bottom
CH10  0.22U_0201_6.3V6M  [C_0201]  189.45 80.84 0 bottom
CH11  0.22U_0201_6.3V6M  [C_0201]  187.99 79.72 0 bottom
CH12  0.22U_0201_6.3V6M  [C_0201]  187.99 79.09 0 bottom
CH13  0.22U_0201_6.3V6M  [C_0201]  189.45 77.85 0 bottom
CH14  0.22U_0201_6.3V6M  [C_0201]  189.45 78.49 0 bottom
CH15  0.22U_0201_6.3V6M  [C_0201]  188.18 77.41 0 bottom
CH16  0.22U_0201_6.3V6M  [C_0201]  188.18 76.77 0 bottom
CH17  0.22U_0201_6.3V6M  [C_0201]  190.02 75.95 0 bottom
CH18  0.22U_0201_6.3V6M  [C_0201]  190.02 76.58 0 bottom
CH19  0.22U_0201_6.3V6M  [C_0201]  188.56 74.93 0 bottom
CH20  0.22U_0201_6.3V6M  [C_0201]  188.56 75.57 0 bottom
CH21  0.22U_0201_6.3V6M  [C_0201]  190.02 74.55 0 bottom
CH22  0.22U_0201_6.3V6M  [C_0201]  190.02 73.92 0 bottom
CH23  0.22U_0201_6.3V6M  [C_0201]  188.62 72.96 0 bottom
CH24  0.22U_0201_6.3V6M  [C_0201]  188.62 73.6 0 bottom
CH25  0.22U_0201_6.3V6M  [C_0201]  190.02 72.52 0 bottom
CH26  0.22U_0201_6.3V6M  [C_0201]  190.02 71.88 0 bottom
CH27  0.22U_0201_6.3V6M  [C_0201]  188.62 70.8 0 bottom
CH28  0.22U_0201_6.3V6M  [C_0201]  188.62 71.44 0 bottom
CH29  0.22U_0201_6.3V6M  [C_0201]  190.02 70.42 0 bottom
CH30  0.22U_0201_6.3V6M  [C_0201]  190.02 69.79 0 bottom
CH31  0.22U_0201_6.3V6M  [C_0201]  188.68 68.26 0 bottom
CH32  0.22U_0201_6.3V6M  [C_0201]  188.68 68.9 0 bottom
CH33  0.22U_0201_6.3V6M  [C_0201]  190.08 67.76 0 bottom
CH34  0.22U_0201_6.3V6M  [C_0201]  190.08 67.12 0 bottom
CH35  0.22U_0201_6.3V6M  [C_0201]  189.32 65.58 0 bottom
CH36  0.22U_0201_6.3V6M  [C_0201]  189.32 66.21 0 bottom
CH44  0.1U_0201_10V6K  [C_0201]  280.99 5.34 0 top
CH45  10P_0201_50V8J  [C_0201]  70.18 4.7 180 bottom
CH46  10P_0201_50V8J  [C_0201]  71.17 4.7 0 bottom
CH47  15P_0201_50V8J  [C_0201]  103.38 17.27 270 top
CH48  15P_0201_50V8J  [C_0201]  103.38 17.87 90 top
CH50  8.2P_0201_50V8B  [C_0201]  105.26 3.07 180 bottom
CH51  10P_0201_25V8  [C_0201]  106.4 3.32 0 bottom
CH52  1U_0402_6.3V6K  [C_0402]  71.83 6.48 180 top
CH53  1U_0402_6.3V6K  [C_0402]  75.44 6.15 270 top
CH70  0.1U_0201_10V6K  [C_0201]  73.76 4.64 180 top
CH80  1U_0201_10V6M  [C_0201]  74.22 2.01 180 top
CH82  0.1U_0201_10V6K  [C_0201]  90.3 6.26 270 top
CH92  4.7U_0402_6.3V6M  [C_0402]  94.59 14.23 270 top
CH100  0.022U_0402_25V7K  [C_0402]  231.31 20.89 270 top
CH101  0.022U_0402_25V7K  [C_0402]  124.88 19.93 270 top
CH102  10U_0402_6.3V6M  [C_0402]  173.15 71.82 270 top
CH103  10U_0402_6.3V6M  [C_0402]  173.18 73.62 270 top
CH104  10U_0402_6.3V6M  [C_0402]  171.76 71.9 270 top
CH105  1U_0402_6.3V6K  [C_0402]  174.87 81.65 0 top
CH106  1U_0402_6.3V6K  [C_0402]  174.45 83.15 45 top
CH107  10U_0402_6.3V6M  [C_0402]  172.95 79.05 0 top
CH108  10U_0402_6.3V6M  [C_0402]  173.1 79.95 0 top
CH109  1U_0402_6.3V6K  [C_0402]  173.1 76.96 270 top
CH110  10U_0402_6.3V6M  [C_0402]  172.95 78.16 0 top
CH111  10U_0402_6.3V6M  [C_0402]  171.08 80.23 180 top
CH112  10U_0402_6.3V6M  [C_0402]  174.56 88.32 180 top
CH113  10U_0402_6.3V6M  [C_0402]  173.61 86.52 90 top
CH114  10U_0402_6.3V6M  [C_0402]  177.9 88.13 0 top
CH115  10U_0402_6.3V6M  [C_0402]  171.18 86.97 180 top
CH116  10U_0402_6.3V6M  [C_0402]  172.7 86.5 90 top
CH117  10U_0402_6.3V6M  [C_0402]  178.15 86.41 0 top
CH118  10U_0402_6.3V6M  [C_0402]  149.66 66.8 0 top
CH119  10U_0402_6.3V6M  [C_0402]  160.49 62.48 90 top
CH120  10U_0402_6.3V6M  [C_0402]  170.33 62.72 270 top
CH121  10U_0402_6.3V6M  [C_0402]  149.68 65.01 0 top
CH122  10U_0402_6.3V6M  [C_0402]  157.1 67.8 90 top
CH123  10U_0402_6.3V6M  [C_0402]  162.6 62.35 90 top
CH124  10U_0402_6.3V6M  [C_0402]  149.66 65.91 0 top
CH125  10U_0402_6.3V6M  [C_0402]  158.83 68.47 0 top
CH126  10U_0402_6.3V6M  [C_0402]  167.8 62.72 270 top
CH127  10U_0402_6.3V6M  [C_0402]  169.42 67.74 0 top
CH128  10U_0402_6.3V6M  [C_0402]  173.66 64.28 0 top
CH129  22U_0603_6.3V6M  [C_0603]  174.88 61.89 90 top
CH130  22U_0603_6.3V6M  [C_0603]  177.29 62.29 90 top
CH131  22U_0603_6.3V6M  [C_0603]  178.56 61.91 90 top
CH132  22U_0603_6.3V6M  [C_0603]  172.86 61.93 90 top
CH133  1U_0201_6.3V6M  [C_0201]  170.73 86.24 180 top
CH134  22U_0603_6.3V6M  [C_0603]  170.79 88.33 180 top
CH135  22U_0603_6.3V6M  [C_0603]  171.03 84.72 180 top
CH136  47U_0805_6.3V6M  [C_0805]  167.51 92.24 90 bottom
CH138  47U_0805_6.3V6M  [C_0805]  169.29 92.24 90 bottom
CH174  0.1U_0402_25V6  [C_0402]  60.1 23.71 180 top
CH175  0.1U_0402_25V6  [C_0402]  122.64 96.08 270 bottom
CH176  1U_0402_10V6K  [C_0402]  85.98 14.73 0 top
CH177  22U_0402_6.3V6M  [C_0402]  101.41 20.45 0 bottom
CH178  22U_0402_6.3V6M  [C_0402]  101.43 19.5 0 bottom
CH179  1U_0201_10V6M  [C_0201]  101.91 21.59 0 bottom
CH180  1U_0201_10V6M  [C_0201]  71 25.88 270 bottom
CH181  4.7U_0402_6.3V6M  [C_0402]  72.01 27.62 90 bottom
CH182  4.7U_0402_6.3V6M  [C_0402]  70.78 27.58 90 bottom
CH183  1U_0201_10V6M  [C_0201]  87.59 17.62 270 top
CH184  22U_0402_6.3V6M  [C_0402]  89.99 17.95 270 top
CH187  1U_0201_10V6M  [C_0201]  94.69 7.58 90 top
CH188  1U_0201_10V6M  [C_0201]  67.13 18.16 180 top
CH189  0.1U_0201_10V6K  [C_0201]  80.02 19.37 180 top
CH190  0.1U_0201_10V6K  [C_0201]  79.66 16.33 90 top
CH191  0.1U_0201_10V6K  [C_0201]  100.33 2.54 180 top
CH192  0.1U_0201_10V6K  [C_0201]  88.43 20.27 90 top
CH196  15P_0201_50V8J  [C_0201]  280.99 4.7 0 top
CH197  0.1U_0402_10V7K  [C_0402]  121.37 53.68 180 top
CH198  15P_0402_50V8J  [C_0402]  80.9 5.26 90 top
CH200  0.1U_0201_10V6K  [C_0201]  93.35 6.17 270 top
CH201  4.7U_0402_6.3V6M  [C_0402]  86.81 17.76 270 top
CH202  4.7U_0402_6.3V6M  [C_0402]  102.36 27.88 270 bottom
CH203  0.1U_0201_10V6K  [C_0201]  101.26 25.83 0 top
CH204  0.1U_0201_10V6K  [C_0201]  90.93 6.26 270 top
CH205  1U_0201_10V6M  [C_0201]  95.33 13.98 270 top
CH206  1U_0402_10V6K  [C_0402]  86.65 15.84 0 top
CH207  1U_0201_10V6M  [C_0201]  99.18 26.96 180 top
CH3320  2P_0201_25V8B  [C_0201]  92.71 6.12 270 top
CH3321  2P_0201_25V8B  [C_0201]  87.64 10.25 270 top
CH3322  2P_0201_25V8B  [C_0201]  101.26 25.25 0 top
CH3323  2P_0201_25V8B  [C_0201]  102.79 24.6 90 top
CH3324  0.1U_0201_10V6K  [C_0201]  91.15 18.2 270 top
CH3327  10P_0402_50V8J  [C_0402]  64.53 5.84 90 top
CH3329  1U_0201_10V6M  [C_0201]  74.96 1.47 180 bottom
CH3331  0.1U_0201_6.3V6K  [C_0201]  74.96 3.25 90 top
CH3332  1U_0201_6.3V6M  [C_0201]  173.34 65.77 270 top
CH3333  1U_0201_6.3V6M  [C_0201]  142.96 68.26 0 top
CH3334  4.7U_0402_6.3V6M  [C_0402]  181.12 80.27 180 top
CI1  0.1U_0402_25V6  [C_0402]  27.69 95.92 90 top
CI2  0.1U_0402_25V6  [C_0402]  330.46 61.1 270 bottom
CI3  0.1U_0402_10V7K  [C_0402]  326.26 33.35 270 top
CI4  0.01U_0402_16V7K  [C_0402]  319.15 37.9 90 top
CI5  0.1U_0402_10V7K  [C_0402]  324.49 40.13 270 top
CI6  0.1U_0402_10V7K  [C_0402]  323.34 40.13 270 top
CI7  0.1U_0402_10V7K  [C_0402]  322.2 40.13 270 top
CI8  0.1U_0402_10V7K  [C_0402]  321.18 40.13 270 top
CI9  0.1U_0201_10V6K  [C_0201]  22.43 106.68 180 bottom
CI10  0.1U_0201_10V6K  [C_0201]  22.43 105.79 180 bottom
CI11  47U_0805_6.3V6M  [C_0805]  20.26 108.62 90 top
CI12  10U_0603_6.3V6M  [C_0603]  18.8 108.52 270 top
CI13  0.1U_0402_25V6  [C_0402]  18.86 109.84 90 top
CI16  0.1U_0402_10V7K  [C_0402]  323.85 32.13 270 top
CI17  47U_0805_6.3V6M  [C_0805]  331.43 69.98 180 bottom
CI18  10U_0603_6.3V6M  [C_0603]  331.03 68.45 180 bottom
CI19  0.1U_0402_25V6  [C_0402]  331.1 67.37 180 bottom
CI20  0.1U_0402_10V7K  [C_0402]  324.74 32.13 270 top
CI21  0.1U_0402_10V7K  [C_0402]  19.43 104.32 90 bottom
CI22  0.1U_0402_10V7K  [C_0402]  324.63 53.98 90 top
CLRP1  SHORT PADS  [SHORTPADS]  67.18 4.57 180 bottom
CM1  0.47U_0201_6.3V6K  [C_0201]  27.69 78.19 90 bottom
CM2  10U_0402_10V6M  [C_0402]  25.22 76.38 90 bottom
CM3  0.1U_0201_10V6K  [C_0201]  24.46 77 270 bottom
CM4  0.1U_0201_10V6K  [C_0201]  23.58 70.99 0 bottom
CM5  0.1U_0201_10V6K  [C_0201]  23.12 77 270 bottom
CM6  0.1U_0201_6.3V6K  [C_0201]  19.43 68.96 270 top
CM7  0.1U_0201_6.3V6K  [C_0201]  20.07 68.96 270 top
CM8  0.47U_0201_6.3V6K  [C_0201]  17.08 68.47 180 bottom
CM9  10U_0402_10V6M  [C_0402]  21.01 71.88 0 bottom
CM10  0.1U_0201_10V6K  [C_0201]  21.76 70.54 180 bottom
CM11  0.1U_0201_10V6K  [C_0201]  22.65 69.62 180 bottom
CM12  0.1U_0201_10V6K  [C_0201]  22.65 69.06 180 bottom
CM13  0.01U_0201_16V7  [C_0201]  21.17 71.12 0 bottom
CM14  0.1U_0201_6.3V6K  [C_0201]  21.46 68.96 270 top
CM15  0.1U_0201_6.3V6K  [C_0201]  22.1 68.96 270 top
CM16  0.1U_0201_6.3V6K  [C_0201]  22.86 69 270 top
CM17  0.1U_0201_6.3V6K  [C_0201]  23.5 69 270 top
CM18  0.1U_0201_6.3V6K  [C_0201]  24.39 68.96 270 top
CM19  0.1U_0201_6.3V6K  [C_0201]  25.02 68.96 270 top
CM20  0.1U_0201_6.3V6K  [C_0201]  17.86 70.23 180 top
CM21  0.1U_0201_6.3V6K  [C_0201]  17.86 70.82 180 top
CM22  0.47U_0201_6.3V6K  [C_0201]  17.95 76.46 180 bottom
CM23  10U_0402_10V6M  [C_0402]  21.08 76.63 90 bottom
CM24  0.1U_0201_10V6K  [C_0201]  22.35 73.06 90 bottom
CM25  0.01U_0201_16V7  [C_0201]  21.85 76.8 90 bottom
CM26  0.47U_0201_6.3V6K  [C_0201]  23.98 68.72 90 bottom
CM27  10U_0402_10V6M  [C_0402]  26.98 68.58 0 bottom
CM28  0.1U_0201_10V6K  [C_0201]  27.85 73.53 180 bottom
CM29  0.1U_0201_10V6K  [C_0201]  27.79 69.53 180 bottom
CM30  0.1U_0201_10V6K  [C_0201]  27.85 72.77 180 bottom
CM31  0.01U_0201_16V7  [C_0201]  27.2 70.3 0 bottom
CM32  0.01U_0201_16V7  [C_0201]  27.2 71.76 0 bottom
CM33  0.01U_0201_16V7  [C_0201]  27.27 74.17 0 bottom
CM34  10U_0402_10V6M  [C_0402]  19.64 74.68 180 bottom
CM35  0.1U_0201_10V6K  [C_0201]  18.89 73.92 0 bottom
CM37  0.47U_0201_6.3V6K  [C_0201]  17.08 69.06 180 bottom
CM38  0.1U_0201_10V6K  [C_0201]  18.76 72.14 0 bottom
CM39  0.01U_0201_16V7  [C_0201]  20.28 73.41 0 bottom
CM40  0.1U_0201_10V6K  [C_0201]  20.78 95.25 180 bottom
CM41  1U_0201_6.3V6M  [C_0201]  20.7 66.68 90 top
CM43  15P_0402_50V8J  [C_0402]  16.31 73.86 270 top
CM44  15P_0402_50V8J  [C_0402]  16.29 74.77 90 top
CM45  0.1U_0201_6.3V6K  [C_0201]  16.15 70.77 180 top
CM46  0.1U_0201_6.3V6K  [C_0201]  16.15 71.4 180 top
CM50  0.01U_0201_16V7  [C_0201]  19.34 72.77 180 bottom
CN1  22U_0603_6.3V6M  [C_0603]  335.59 98.41 0 top
CN2  .1U_0402_16V7K  [C_0402]  336.12 97.37 0 top
CN6  22U_0603_6.3V6M  [C_0603]  347.43 87.9 0 top
CN7  .1U_0402_16V7K  [C_0402]  346.45 88.06 180 top
CN8  .1U_0402_16V7K  [C_0402]  336.15 99.48 0 top
CN9  1000P_0201_50V7K  [C_0201]  336.59 100.23 0 top
CN20  0.1U_0201_10V6K  [C_0201]  331.43 81.15 0 bottom
CN21  0.1U_0201_10V6K  [C_0201]  331.43 80.27 0 bottom
CN22  2200P_0402_25V7K  [C_0402]  337.11 105.28 0 top
CR1  0.1U_0201_10V6K  [C_0201]  334.65 37.43 90 bottom
CR2  0.1U_0201_10V6K  [C_0201]  335.79 38.77 270 bottom
CR3  1U_0402_6.3V6K  [C_0402]  337.54 41.3 90 bottom
CR4  10U_0603_6.3V6M  [C_0603]  332.93 37.47 180 bottom
CR5  0.1U_0201_10V6K  [C_0201]  335.98 33.99 270 bottom
CR6  4.7U_0603_6.3V6K  [C_0603]  332.93 38.67 180 bottom
CR7  0.1U_0402_10V7K  [C_0402]  341.38 33.07 90 bottom
CR8  10P_0201_50V8J  [C_0201]  335.15 42.24 270 bottom
CR9  0.1U_0402_10V7K  [C_0402]  340.49 33.07 90 bottom
CR10  0.1U_0402_10V7K  [C_0402]  338.71 33.07 90 bottom
CR11  0.1U_0201_10V6K  [C_0201]  344.55 38.13 90 bottom
CR12  4.7U_0402_6.3V6M  [C_0402]  345.31 37.71 90 bottom
CR13  0.1U_0402_10V7K  [C_0402]  337.76 33.07 90 bottom
CR14  10U_0603_6.3V6M  [C_0603]  328.13 50.48 270 top
CR15  0.1U_0201_10V6K  [C_0201]  328.13 51.42 90 top
CR16  1U_0402_6.3V6K  [C_0402]  343.35 40.18 90 bottom
CR17  4.7U_0603_6.3V6K  [C_0603]  349.77 46.86 0 bottom
CR18  0.1U_0402_10V7K  [C_0402]  350.19 45.47 0 bottom
CS12  1000P_0402_50V7K  [C_0402]  238.06 13.01 90 bottom
CS13  .1U_0402_16V7K  [C_0402]  239.02 13.01 90 bottom
CS14  1U_0402_6.3V6K  [C_0402]  238.68 11.18 0 top
CS15  10U_0603_6.3V6M  [C_0603]  240.09 12.76 90 bottom
CS17  0.01U_0201_16V7  [C_0201]  233.27 13.22 270 bottom
CS18  0.01U_0201_16V7  [C_0201]  233.91 13.22 270 bottom
CS19  0.01U_0201_16V7  [C_0201]  235.43 13.22 270 bottom
CS20  0.01U_0201_16V7  [C_0201]  234.79 13.22 270 bottom
CT1  0.22U_0201_6.3V6M  [C_0201]  24.5 32.54 90 bottom
CT2  0.22U_0201_6.3V6M  [C_0201]  25.73 33.06 270 bottom
CT3  0.22U_0201_6.3V6M  [C_0201]  25.07 32.54 90 bottom
CT4  0.22U_0201_6.3V6M  [C_0201]  26.29 33.06 270 bottom
CT5  0.22U_0201_6.3V6M  [C_0201]  26.87 32.53 90 bottom
CT6  0.22U_0201_6.3V6M  [C_0201]  28.12 33.11 270 bottom
CT7  0.22U_0201_6.3V6M  [C_0201]  27.43 32.53 90 bottom
CT8  0.22U_0201_6.3V6M  [C_0201]  28.69 33.11 270 bottom
CT17  0.1U_0201_6.3V6K  [C_0201]  34.76 43.05 0 bottom
CT18  0.1U_0201_6.3V6K  [C_0201]  34.76 42.42 0 bottom
CT19  0.1U_0201_6.3V6K  [C_0201]  35.46 40.64 0 bottom
CT20  0.1U_0201_6.3V6K  [C_0201]  35.46 41.28 0 bottom
CT21  0.1U_0201_6.3V6K  [C_0201]  34.13 39.75 0 bottom
CT22  0.1U_0201_6.3V6K  [C_0201]  34.13 40.39 0 bottom
CT23  0.1U_0201_6.3V6K  [C_0201]  35.78 38.79 0 bottom
CT24  0.1U_0201_6.3V6K  [C_0201]  35.78 39.37 0 bottom
CT25  0.1U_0201_6.3V6K  [C_0201]  33.36 40.01 0 top
CT26  0.1U_0201_6.3V6K  [C_0201]  33.36 40.58 0 top
CT29  0.1U_0201_6.3V6K  [C_0201]  34.51 37.66 0 bottom
CT30  0.1U_0201_6.3V6K  [C_0201]  34.51 38.29 0 bottom
CT31  0.1U_0201_6.3V6K  [C_0201]  36.23 36.53 0 bottom
CT32  0.1U_0201_6.3V6K  [C_0201]  36.23 37.16 0 bottom
CT33  0.1U_0201_6.3V6K  [C_0201]  37.81 35.05 0 bottom
CT34  0.1U_0201_6.3V6K  [C_0201]  37.81 35.69 0 bottom
CT35  0.1U_0201_6.3V6K  [C_0201]  35.78 34.09 0 bottom
CT36  0.1U_0201_6.3V6K  [C_0201]  35.78 34.67 0 bottom
CT37  0.22U_0201_6.3V6M  [C_0201]  18.64 38.51 180 bottom
CT38  0.22U_0201_6.3V6M  [C_0201]  18.64 39.08 180 bottom
CT39  0.22U_0201_6.3V6M  [C_0201]  20.03 37.07 180 bottom
CT40  0.22U_0201_6.3V6M  [C_0201]  20.03 37.64 180 bottom
CT41  0.1U_0201_6.3V6K  [C_0201]  33.62 38.16 0 top
CT42  0.1U_0201_6.3V6K  [C_0201]  33.62 37.59 0 top
CT43  27P_0201_25V8  [C_0201]  22.1 32.39 90 bottom
CT44  27P_0201_25V8  [C_0201]  22.1 31.75 270 bottom
CT47  0.1U_0201_6.3V6K  [C_0201]  40.41 24.07 90 top
CT50  1U_0201_6.3V6M  [C_0201]  34.63 42.24 270 top
CT52  1U_0201_6.3V6M  [C_0201]  19.01 45.78 90 bottom
CT53  10U_0402_6.3V6M  [C_0402]  17.98 42.84 0 bottom
CT54  10U_0402_6.3V6M  [C_0402]  17.99 41.94 0 bottom
CT55  10U_0402_6.3V6M  [C_0402]  19.74 45.38 90 bottom
CT56  10U_0402_6.3V6M  [C_0402]  17.98 43.75 0 bottom
CT62  1U_0201_6.3V6M  [C_0201]  26.6 44.87 90 top
CT63  1U_0201_6.3V6M  [C_0201]  28.03 42.93 0 top
CT64  1U_0201_6.3V6M  [C_0201]  27.17 44.87 90 top
CT65  1U_0201_6.3V6M  [C_0201]  27.22 39.47 180 top
CT66  1U_0201_6.3V6M  [C_0201]  30.65 37.49 180 top
CT67  1U_0201_6.3V6M  [C_0201]  31.75 37.38 270 top
CT68  1U_0201_6.3V6M  [C_0201]  32.39 37.38 270 top
CT71  1U_0201_6.3V6M  [C_0201]  28.39 35.09 270 top
CT72  1U_0201_6.3V6M  [C_0201]  29.05 35.24 0 top
CT74  1U_0201_6.3V6M  [C_0201]  22.26 42.72 180 top
CT80  1U_0201_6.3V6M  [C_0201]  26.1 35.09 270 top
CT81  1U_0201_6.3V6M  [C_0201]  27.24 35.09 270 top
CT82  1U_0201_6.3V6M  [C_0201]  27.81 35.09 270 top
CT83  1U_0201_6.3V6M  [C_0201]  22.26 42.14 180 top
CT84  1U_0201_6.3V6M  [C_0201]  22.26 43.31 180 top
CT85  1U_0201_6.3V6M  [C_0201]  22.26 40.97 180 top
CT86  1U_0201_6.3V6M  [C_0201]  22.26 41.56 180 top
CT88  47U_0603_6.3V6M  [C_0603]  23.61 44.84 180 top
CT89  47U_0603_6.3V6M  [C_0603]  23.24 46.04 90 top
CT90  47U_0603_6.3V6M  [C_0603]  22.16 47.37 180 top
CT93  1U_0201_6.3V6M  [C_0201]  28.55 36.86 180 top
CT94  1U_0201_6.3V6M  [C_0201]  28.79 37.47 0 top
CT95  10U_0402_6.3V6M  [C_0402]  22.06 37.81 180 top
CT96  10U_0402_6.3V6M  [C_0402]  22.05 36.89 180 top
CT97  10U_0402_6.3V6M  [C_0402]  22.06 39.6 180 top
CT98  10U_0402_6.3V6M  [C_0402]  22.06 38.71 180 top
CT99  1U_0201_6.3V6M  [C_0201]  25.49 37.54 270 top
CT100  1U_0201_6.3V6M  [C_0201]  25.46 38.16 90 top
CT101  1U_0201_6.3V6M  [C_0201]  31.79 43.44 180 top
CT102  1U_0201_6.3V6M  [C_0201]  32.3 42.17 180 top
CT103  1U_0201_6.3V6M  [C_0201]  32.32 42.79 180 top
CT107  0.1U_0201_6.3V6K  [C_0201]  33.36 38.8 0 top
CT108  0.1U_0201_6.3V6K  [C_0201]  33.36 39.37 0 top
CT120  0.47U_0402_25V6K  [C_0402]  12 67.2 270 bottom
CT121  0.47U_0402_25V6K  [C_0402]  11.11 67.2 270 bottom
CT122  0.47U_0402_25V6K  [C_0402]  8.07 65.36 270 bottom
CT123  0.47U_0402_25V6K  [C_0402]  12.37 63.89 270 bottom
CT141  1U_0201_6.3V6M  [C_0201]  22.24 43.87 180 top
CT142  1U_0201_6.3V6M  [C_0201]  22.26 40.39 180 top
CT143  1U_0201_6.3V6M  [C_0201]  24.3 41.53 180 top
CT144  2.2U_0402_6.3V6M  [C_0402]  16.64 58.29 90 bottom
CT145  1U_0201_6.3V6M  [C_0201]  21.83 59.97 0 top
CT146  10U_0402_6.3V6M  [C_0402]  20.45 58.75 270 top
CT147  22U_0603_6.3V6M  [C_0603]  28.39 54.48 0 bottom
CT148  22U_0603_6.3V6M  [C_0603]  28.39 55.75 0 bottom
CT149  22U_0603_6.3V6M  [C_0603]  28.98 56.82 90 bottom
CT150  22U_0603_6.3V6M  [C_0603]  27.77 56.83 90 bottom
CT151  2.2U_0402_6.3V6M  [C_0402]  19.19 61.09 180 bottom
